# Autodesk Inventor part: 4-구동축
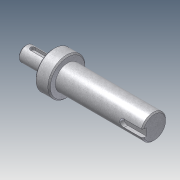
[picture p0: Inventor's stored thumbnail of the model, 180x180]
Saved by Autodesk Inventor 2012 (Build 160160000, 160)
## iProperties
Created: 2012-07
Part Number: 4-구동축
Document SubType Name: Modeling
Designer: SeoGD™ [www.esajin.kr]
Density: 1 g/cm^3
Material: 기본값
Author: SeoGD™ [www.esajin.kr]
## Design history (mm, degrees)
sketch "스케치1"
  geometry: L1 (34.997, -37.5)-(34.997, -77.5) reference; L2 (46.5, -38.401)-(46.5, -76.599) reference; L3 (12.497, -57.5)-(116.5, -57.5); L4 (12.497, -63.5)-(34.997, -63.5); L5 (34.997, -72.5)-(46.5, -72.5); L6 (46.5, -67.5)-(116.5, -67.5); L7 (116.5, -67.5)-(116.5, -57.5); L8 (12.497, -63.5)-(12.497, -57.5); 2 further points
  constraints: 12 end point, 5 point on line, 4 perpendicular, 1 midpoint, 1 parallel
  dimensions: "d0" = 20 diameter of L6 L3; "d1" = 30 diameter of L5 L3; "d2" = 22.5 distance of L4.start L4.end; "d3" = 70 distance of L6.start L6.end; "d5" = 12 diameter of L4 L3
revolve "회전1" sketch "스케치1" stored, may be unused: angle "d4" = 90 deg
chamfer "모따기1" distance "d6" = 1; stored, may be unused: second distance "d7" = 2, angle "d8" = 45 deg
node "작업 평면1"
sketch "스케치2"
  geometry: L1 (-11.25, -5)-(-11.25, 5) reference; L2 (-5.25, 2)-(4.75, 2); L3 (4.75, -2)-(-5.25, -2); A1 r 2 centre (4.75, 0) between (4.75, -2) and (4.75, 2); A2 r 2 centre (-5.25, 0) between (-5.25, 2) and (-5.25, -2); 2 further points
  constraints: 4 end point, 4 point on circle, 4 tangent, 2 centre point, 1 horizontal alignment, 1 midpoint, 1 parallel, 1 perpendicular
  dimensions: "d9" = 4 distance between parallel lines of L3 L2; "d10" = 14 dimension on A1 A2; "d11" = 4 distance edge to line of A2 L1
extrude "돌출1" cut sketch "스케치2" distance "d12" = 2.5; taper "d13" = 0 deg
node "작업 평면2"
sketch "스케치3"
  geometry: L1 (35, 9)-(35, -9) reference; L2 (35, 3)-(20, 3); L3 (20, -3)-(35, -3); A1 r 3 centre (20, 0) between (20, 3) and (20, -3); 2 further points
  constraints: 4 end point, 2 perpendicular, 2 point on circle, 2 point on line, 2 tangent, 1 centre point, 1 horizontal alignment, 1 midpoint
  dimensions: "d14" = 6 distance between parallel lines of L3 L2; "d15" = 18 dimension on A1 L1
extrude "돌출2" cut sketch "스케치3" distance "d16" = 3.5; taper "d17" = 0 deg
node "솔리드1"
node "참조1"
node "참조2"
